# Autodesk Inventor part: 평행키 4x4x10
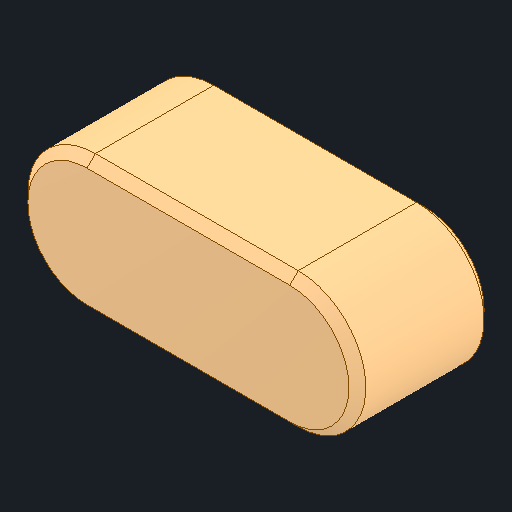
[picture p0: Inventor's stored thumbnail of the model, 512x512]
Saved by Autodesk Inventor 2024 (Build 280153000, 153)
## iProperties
Created: 2025-02
Part Number: 평행키 4x4x10
Material: 강철, 연강
Description: 키 및 해당 키홈
Document SubType Name: Modeling
Designer: kh_501
Density: 7.85 g/cm^3
Appearance: 기본값
Author: jhkim
Sending System: Autodesk Inventor 2025
Preprocessor: ST-DEVELOPER v20
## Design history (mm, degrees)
feature "Solid1"
node "솔리드1"
